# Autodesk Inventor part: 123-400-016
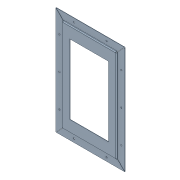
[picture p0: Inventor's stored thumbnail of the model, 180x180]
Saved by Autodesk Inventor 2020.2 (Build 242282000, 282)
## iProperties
Manager: www.cadconsulting.pl
Company: Fabian Stasiak CAD Consulting
Created: 2019-11
Part Number: 123-400-016
Material: Stal
Document SubType Name: Konstrukcja blachowa
Designer: F.Stasiak
Density: 7.85 g/cm^3
Sheet Metal Rule: Domyślny_mm
Appearance: Stalowoniebieska
Description: Ramka
Author: F.Stasiak
Subject: Zbiór ćwiczeń. Autodesk Inventor 2020. Kurs podstawowy
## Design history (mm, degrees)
node "Powierzchnia1"
  sketch "Szkic1"
    geometry: L1 (175, -300)-(-175, -300); L2 (-175, -300)-(-175, 300); L3 (-175, 300)-(175, 300); L4 (175, 300)-(175, -300); L5 (175, -300)-(-175, 300); L6 (-175, -300)-(175, 300); 1 further point
    constraints: 12 end point, 2 midpoint, 2 parallel, 1 horizontal, 1 perpendicular
    dimensions: "d0" = 350 distance of L2.end L3.end; "d1" = 600 distance of L1.end L2.end
node "Kołnierz1"
node "Kołnierz2"
sketch "Szkic4"
  geometry: L1 (-125, 225)-(125, 225); L2 (125, 225)-(125, -225); L3 (125, -225)-(-125, -225); L4 (-125, -225)-(-125, 225); L5 (-125, 225)-(125, -225); L6 (125, 225)-(-125, -225); 1 further point
  constraints: 12 end point, 2 midpoint, 2 parallel, 1 horizontal, 1 perpendicular
  dimensions: "d23" = 250 distance of L2.end L3.end; "d24" = 450 distance of L1.end L2.end
feature "Wytnij1" sketch "Szkic4" dims "d25" = 2.5 (= Grubość), "d26" = 0
sketch "Szkic5"
  geometry: L1 (0, 0)-(0, 691.464) reference; 3 further points
  constraints: 1 horizontal alignment, 1 midpoint
  dimensions: "d27" = 23 distance from line of L1 point (-23, 345.732)
hole "Otwór1" sketch "Szkic5" at (-23, 345.732) diameter "d28" = 9; stored, may be unused: countersink angle "d32" = 90 deg, drill point angle "d34" = 118 deg; dims "d29" = 6, "d30" = 17.3, "d31" = 2, "d33" = 2.5 (= Grubość)
sketch "Szkic6"
  geometry: L1 (-422, 670.232)-(-23, 670.232); L2 (-23, 670.232)-(-23, 21.232); L3 (-23, 21.232)-(-422, 21.232); L4 (-422, 21.232)-(-422, 670.232); L5 (-422, 670.232)-(-23, 21.232); L6 (-23, 670.232)-(-422, 21.232); L7 (-1.768, 693.232)-(-443.232, 693.232) reference; C1 r 4.5 at (-23, 345.732) reference; 1 further point
  constraints: 12 end point, 3 midpoint, 2 parallel, 1 horizontal, 1 perpendicular
  dimensions: "d35" = 23 distance between parallel lines of L1 L7
pattern_linear "Szyk prostokątny1" sketch "Szkic6"
node "Bryła1"
feature "Płyta1" dims "d2" = 2.5 (= Grubość)
sketch "Szkic2"
  geometry: L1 through (175, 0) direction (-1, 0); L2 through (0, -5) direction (0, -1); L3 (0, -10)-(350, -10); L4 (350, -10)-(350, 0)
  constraints: 6 end point, 1 horizontal, 1 perpendicular, 1 vertical
feature "Płyta2" dims "d2" = 2.5 (= Grubość), "d3" = 2.5 (= SzerokośćGięciaPodcięcia), "d4" = 1.25 (= GłębokośćGięciaPodcięcia), "d5" = 5 (= MinimalnaPozostałość), "d6" = 2.5 (= PromieńPrzejścia), "d7" = 10, "d8" = 90 deg, "d9" = 2.5 (= PromieńGięcia), "d10" = 10 (= RozmiarPodcięciaNarożnika), "d11" = 2.5 (= Wielk_odstępu), "d12" = 2.5 (= Rozmiar_promienia_Jacobiego), "OdstępPołączenia" = 0.01
feature "Zagięcie1" dims "d2" = 2.5 (= Grubość), "d3" = 2.5 (= SzerokośćGięciaPodcięcia), "d4" = 1.25 (= GłębokośćGięciaPodcięcia), "d5" = 5 (= MinimalnaPozostałość), "d6" = 2.5 (= PromieńPrzejścia), "d7" = 10, "d8" = 90 deg, "d9" = 2.5 (= PromieńGięcia), "OdstępPołączenia" = 0.01
feature "Narożnik1" dims "d7" = 10, "d8" = 90 deg, "d10" = 10 (= RozmiarPodcięciaNarożnika), "d11" = 2.5 (= Wielk_odstępu), "d12" = 2.5 (= Rozmiar_promienia_Jacobiego)
sketch "Szkic3"
  geometry: L1 through (-170.732, 0) direction (1, -3.12e-16); L2 through (0, 25) direction (-3.38e-32, 1); L3 (0, 50)-(-341.464, 50); L4 (-341.464, 50)-(-341.464, 0)
  constraints: 6 end point, 1 horizontal, 1 perpendicular, 1 vertical
feature "Płyta3" dims "d2" = 2.5 (= Grubość), "d13" = 2.5 (= SzerokośćGięciaPodcięcia), "d14" = 1.25 (= GłębokośćGięciaPodcięcia), "d15" = 5 (= MinimalnaPozostałość), "d16" = 2.5 (= PromieńPrzejścia), "d17" = 50, "d18" = 90 deg, "d19" = 2.5 (= PromieńGięcia), "d20" = 10 (= RozmiarPodcięciaNarożnika), "d21" = 2.5 (= Wielk_odstępu), "d22" = 2.5 (= Rozmiar_promienia_Jacobiego), "OdstępPołączenia" = 0.01
feature "Zagięcie2" dims "d2" = 2.5 (= Grubość), "d13" = 2.5 (= SzerokośćGięciaPodcięcia), "d14" = 1.25 (= GłębokośćGięciaPodcięcia), "d15" = 5 (= MinimalnaPozostałość), "d16" = 2.5 (= PromieńPrzejścia), "d17" = 50, "d18" = 90 deg, "d19" = 2.5 (= PromieńGięcia), "OdstępPołączenia" = 0.01
feature "Narożnik2" dims "d17" = 50, "d18" = 90 deg, "d20" = 10 (= RozmiarPodcięciaNarożnika), "d21" = 2.5 (= Wielk_odstępu), "d22" = 2.5 (= Rozmiar_promienia_Jacobiego)
other parameters: "Grubość" = 2.5 (derived), "WspółczynnikK" = 4.4, "PromieńGięcia" = 2.5 (= Grubość), "SzerokośćGięciaPodcięcia" = 2.5 (= Grubość), "GłębokośćGięciaPodcięcia" = 1.25 (= 0.5 x Grubość), "MinimalnaPozostałość" = 5 (= 2 x Grubość), "PromieńPrzejścia" = 2.5 (= PromieńGięcia), "Rozmiar_promienia_Jacobiego" = 2.5 (= PromieńGięcia), "Wielk_odstępu" = 2.5 (= Grubość)
